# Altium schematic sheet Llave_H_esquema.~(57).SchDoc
size A4
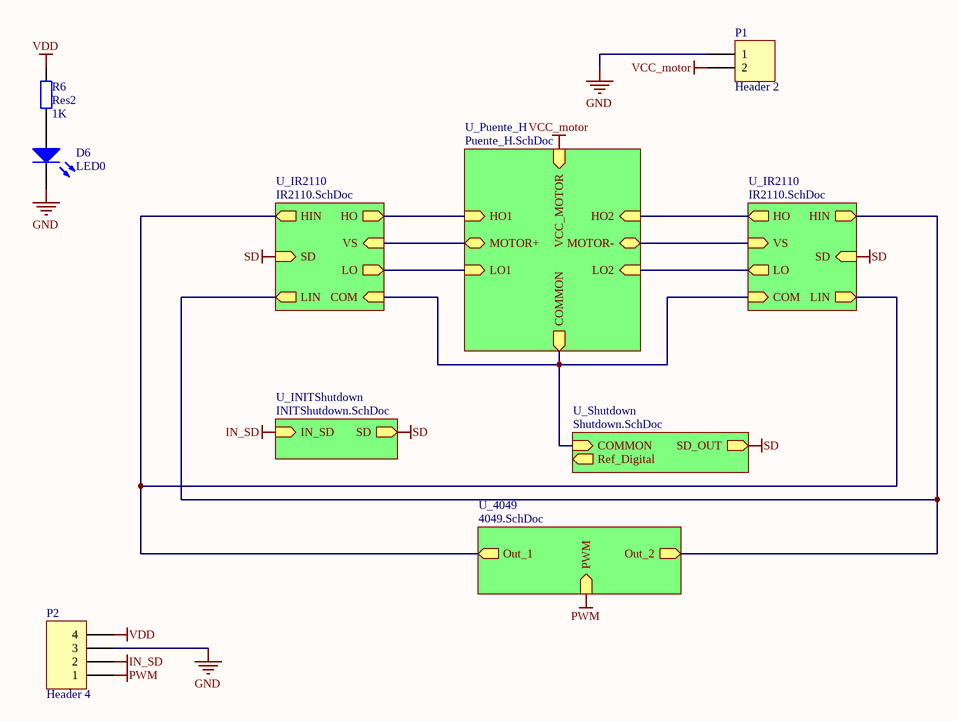
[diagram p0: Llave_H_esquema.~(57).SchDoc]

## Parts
D6  LED0  [CAPPR2.5-6.3X5]
P1  Header 2  [pwheader1x2]
P2  Header 4  [HDR1X5]
R6  Res2  value 1K  [AXIAL-0.3]

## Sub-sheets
U_4049 = 4049.SchDoc: PWM (in), Out_1 (out), Out_2 (out)
U_INITShutdown = INITShutdown.SchDoc: IN_SD (in), SD (out)
U_IR2110 = IR2110.SchDoc: SD (in), HIN (out), LIN (out), HO (out), LO (out), VS (in), COM (in)
U_IR2110 = IR2110.SchDoc: SD (in), HIN (out), LIN (out), HO (out), LO (out), VS (in), COM (in)
U_Puente_H = Puente_H.SchDoc: HO1 (in), LO1 (in), HO2 (in), LO2 (in), MOTOR+ (bidir), MOTOR- (bidir), VCC_MOTOR (in), COMMON (out)
U_Shutdown = Shutdown.SchDoc: COMMON (in), SD_OUT (out), Ref_Digital (out)

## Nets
GND: D6.2(K) P1.1 P2.3
IN_SD: P2.2 ; sheet U_INITShutdown/IN_SD
PWM: P2.1 ; sheet U_4049/PWM
SD: sheet U_IR2110/SD, sheet U_IR2110/SD, sheet U_INITShutdown/SD, sheet U_Shutdown/SD_OUT
VCC_motor: P1.2 ; sheet U_Puente_H/VCC_MOTOR
VDD: P2.4 R6.2
NetD6_1: D6.1(A) R6.1
(unnamed): sheet U_IR2110/HIN, sheet U_IR2110/LIN, sheet U_4049/Out_1
(unnamed): sheet U_IR2110/LIN, sheet U_IR2110/HIN, sheet U_4049/Out_2  [a separate net that carries the same name]
(unnamed): sheet U_IR2110/HO, sheet U_Puente_H/HO1  [a separate net that carries the same name]
(unnamed): sheet U_IR2110/LO, sheet U_Puente_H/LO1  [a separate net that carries the same name]
(unnamed): sheet U_IR2110/VS, sheet U_Puente_H/MOTOR+  [a separate net that carries the same name]
(unnamed): sheet U_IR2110/COM, sheet U_IR2110/COM, sheet U_Puente_H/COMMON, sheet U_Shutdown/COMMON  [a separate net that carries the same name]
(unnamed): sheet U_IR2110/HO, sheet U_Puente_H/HO2  [a separate net that carries the same name]
(unnamed): sheet U_IR2110/LO, sheet U_Puente_H/LO2  [a separate net that carries the same name]
(unnamed): sheet U_IR2110/VS, sheet U_Puente_H/MOTOR-  [a separate net that carries the same name]

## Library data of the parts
D6 = LED0: Typical INFRARED GaAs LED
P1 = Header 2: Header, 2-Pin
P2 = Header 4: Header, 4-Pin
R6 = Res2: Resistor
